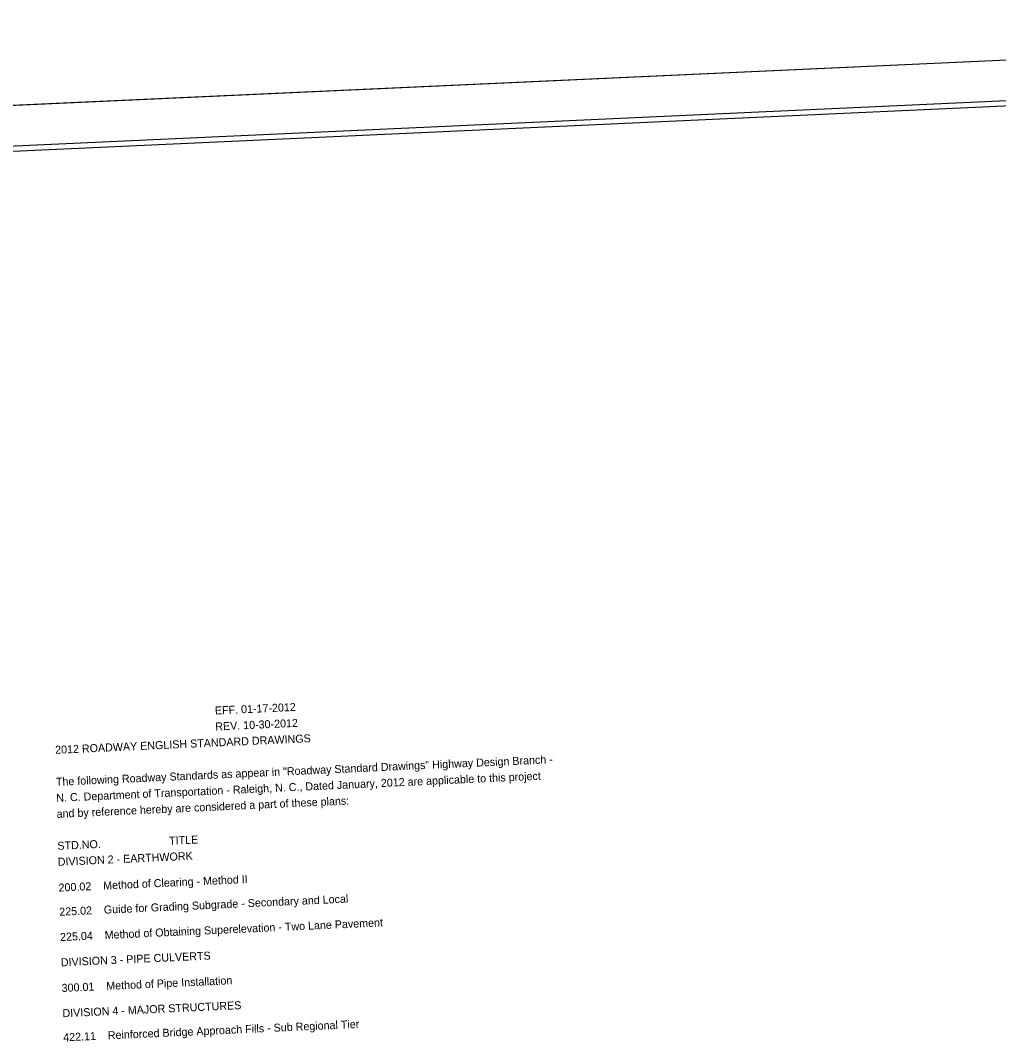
# Model space of a CAD drawing. Extents: x 1190067 to 1192950, y 891516 to 893460.
# Drawn here: x 1191421.2 to 1191613.6, y 892232.8 to 892433.7 of the extents above; entities that cross this region are included whole.
import ezdxf

# ---------------------------------------------------------------- set-up
doc = ezdxf.new("R2010")
doc.units = 0
for name, color, linetype in [('Sheet Cutting Line CELL', 7, 'Continuous'), ('Sheet Data Text CELL', 7, 'Continuous'), ('Sheet Plan CELL', 7, 'Continuous'), ('Sheet Plot Border Inside CELL', 7, 'Continuous'), ('Sheet Plot Border Outside CELL', 7, 'Continuous')]:
    doc.layers.add(name, color=color, linetype=linetype)

msp = doc.modelspace()

# ---------------------------------------------------------------- linework, layer by layer
at = {"layer": 'Sheet Cutting Line CELL'}
msp.add_line((1191785.98, 892433.72), (1191113.28, 892402.94), dxfattribs=at)
at = {"layer": 'Sheet Plan CELL'}
msp.add_lwpolyline([(1191779.6, 892424.42), (1191180.22, 892397), (1191199.42, 891977.44), (1191798.79, 892004.86)], close=True, dxfattribs=at)
at = {"layer": 'Sheet Plot Border Inside CELL'}
msp.add_lwpolyline([(1191138.13, 891973.63), (1191803.83, 892004.09), (1191784.54, 892425.65), (1191118.84, 892395.19)], close=True, dxfattribs=at)
at = {"layer": 'Sheet Plot Border Outside CELL'}
msp.add_lwpolyline([(1191133.3, 891965.4), (1191805.99, 891996.18), (1191785.98, 892433.72), (1191113.28, 892402.94)], close=True, dxfattribs=at)

# ---------------------------------------------------------------- texts
at = {"layer": 'Sheet Data Text CELL'}
for s, height, p in [('                                                      EFF. 01-17-2012', 1.5748, (1191427.94, 892295.69)), ('                                                      REV. 10-30-2012', 1.5748, (1191428.01, 892292.54)), ('2012 ROADWAY ENGLISH STANDARD DRAWINGS', 1.5748, (1191428.08, 892289.4)), ('The following Roadway Standards as appear in "Roadway Standard Drawings" Highway Design Branch -', 1.5748, (1191428.23, 892283.1)), ('N. C. Department of Transportation - Raleigh, N. C., Dated January, 2012 are applicable to this project', 1.57484, (1191428.3, 892279.95)), ('and by reference hereby are considered a part of these plans:', 1.5748, (1191428.37, 892276.8)), ('STD.NO.                       TITLE', 1.5748, (1191428.52, 892270.51)), ('DIVISION 2 - EARTHWORK', 1.5748, (1191428.59, 892267.36)), ('200.02    Method of Clearing - Method II', 1.5748, (1191428.75, 892262.29)), ('225.02    Guide for Grading Subgrade - Secondary and Local', 1.5748, (1191428.89, 892257.54)), ('225.04    Method of Obtaining Superelevation - Two Lane Pavement', 1.5748, (1191429.05, 892252.56)), ('DIVISION 3 - PIPE CULVERTS', 1.5748, (1191429.2, 892247.59)), ('300.01    Method of Pipe Installation ', 1.5748, (1191429.36, 892242.54)), ('DIVISION 4 - MAJOR STRUCTURES', 1.5748, (1191429.52, 892237.57)), ('422.11    Reinforced Bridge Approach Fills - Sub Regional Tier', 1.5748, (1191429.66, 892232.82))]:
    msp.add_text(s, height=height, rotation=2.6195, dxfattribs=at).set_placement(p)

doc.saveas('drawing.dxf')
